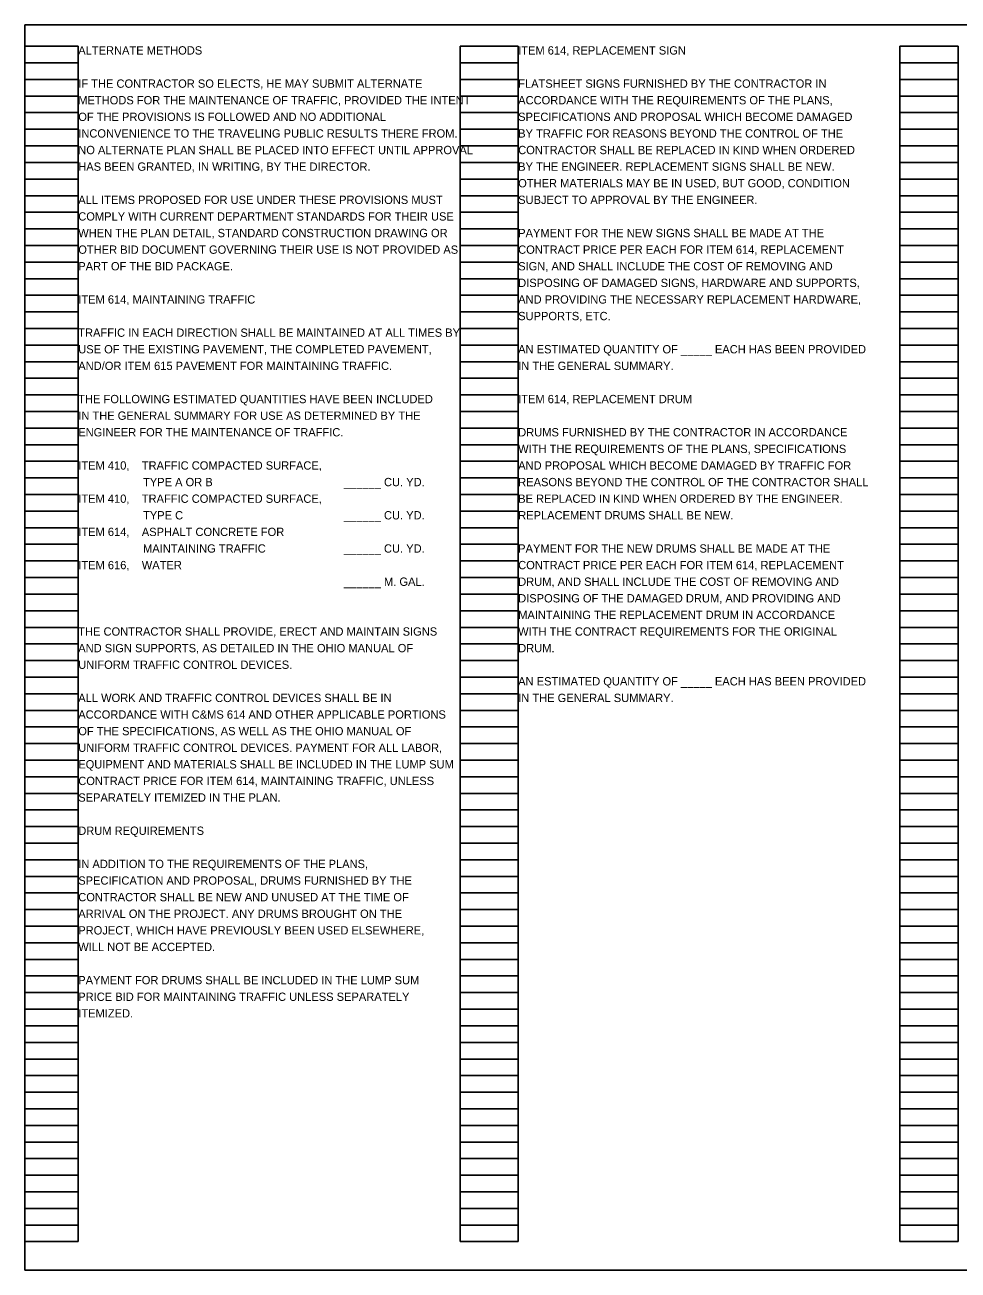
# Model space of a CAD drawing. Extents: x -34 to 2132911, y 0 to 658646.
# Drawn here: x 1.5 to 17.24, y 0.5 to 21.5 of the extents above; entities that cross this region are included whole.
import ezdxf

# ---------------------------------------------------------------- set-up
doc = ezdxf.new("R2010")
doc.units = 0
for name, color, linetype in [('SC_Scratch1', 7, 'Continuous'), ('SH_Data', 7, 'Continuous'), ('SH_Text', 7, 'Continuous')]:
    doc.layers.add(name, color=color, linetype=linetype)

msp = doc.modelspace()

# ---------------------------------------------------------------- linework, layer by layer
at = {"layer": 'SC_Scratch1'}
msp.add_lwpolyline([(1.5, 21.5), (32, 21.5), (32, 0.5), (1.5, 0.5)], close=True, dxfattribs=at)
at = {"layer": 'SH_Data'}
for p, q in [((1.5, 0.98), (1.5, 21.14)), ((1.5, 21.14), (2.4, 21.14)), ((2.4, 0.98), (2.4, 21.14)), ((8.84, 0.98), (8.84, 21.14)), ((8.84, 21.14), (9.82, 21.14)), ((9.82, 0.98), (9.82, 21.14)), ((16.26, 0.98), (16.26, 21.14)), ((16.26, 21.14), (17.24, 21.14)), ((17.24, 0.98), (17.24, 21.14)), ((1.5, 20.86), (2.4, 20.86)), ((8.84, 20.86), (9.82, 20.86)), ((16.26, 20.86), (17.24, 20.86)), ((1.5, 20.58), (2.4, 20.58)), ((8.84, 20.58), (9.82, 20.58)), ((16.26, 20.58), (17.24, 20.58)), ((1.5, 20.3), (2.4, 20.3)), ((8.84, 20.3), (9.82, 20.3)), ((16.26, 20.3), (17.24, 20.3)), ((1.5, 20.02), (2.4, 20.02)), ((8.84, 20.02), (9.82, 20.02)), ((16.26, 20.02), (17.24, 20.02)), ((1.5, 19.74), (2.4, 19.74)), ((8.84, 19.74), (9.82, 19.74)), ((16.26, 19.74), (17.24, 19.74)), ((1.5, 19.46), (2.4, 19.46)), ((8.84, 19.46), (9.82, 19.46)), ((16.26, 19.46), (17.24, 19.46)), ((1.5, 19.18), (2.4, 19.18)), ((8.84, 19.18), (9.82, 19.18)), ((16.26, 19.18), (17.24, 19.18)), ((1.5, 18.9), (2.4, 18.9)), ((8.84, 18.9), (9.82, 18.9)), ((16.26, 18.9), (17.24, 18.9)), ((1.5, 18.62), (2.4, 18.62)), ((8.84, 18.62), (9.82, 18.62)), ((16.26, 18.62), (17.24, 18.62)), ((1.5, 18.34), (2.4, 18.34)), ((8.84, 18.34), (9.82, 18.34)), ((16.26, 18.34), (17.24, 18.34)), ((1.5, 18.06), (2.4, 18.06)), ((8.84, 18.06), (9.82, 18.06)), ((16.26, 18.06), (17.24, 18.06)), ((1.5, 17.78), (2.4, 17.78)), ((8.84, 17.78), (9.82, 17.78)), ((16.26, 17.78), (17.24, 17.78)), ((1.5, 17.5), (2.4, 17.5)), ((8.84, 17.5), (9.82, 17.5)), ((16.26, 17.5), (17.24, 17.5)), ((1.5, 17.22), (2.4, 17.22)), ((8.84, 17.22), (9.82, 17.22)), ((16.26, 17.22), (17.24, 17.22)), ((1.5, 16.94), (2.4, 16.94)), ((8.84, 16.94), (9.82, 16.94)), ((16.26, 16.94), (17.24, 16.94)), ((1.5, 16.66), (2.4, 16.66)), ((8.84, 16.66), (9.82, 16.66)), ((16.26, 16.66), (17.24, 16.66)), ((1.5, 16.38), (2.4, 16.38)), ((8.84, 16.38), (9.82, 16.38)), ((16.26, 16.38), (17.24, 16.38)), ((1.5, 16.1), (2.4, 16.1)), ((8.84, 16.1), (9.82, 16.1)), ((16.26, 16.1), (17.24, 16.1)), ((1.5, 15.82), (2.4, 15.82)), ((8.84, 15.82), (9.82, 15.82)), ((16.26, 15.82), (17.24, 15.82)), ((1.5, 15.54), (2.4, 15.54)), ((8.84, 15.54), (9.82, 15.54)), ((16.26, 15.54), (17.24, 15.54)), ((1.5, 15.26), (2.4, 15.26)), ((8.84, 15.26), (9.82, 15.26)), ((16.26, 15.26), (17.24, 15.26)), ((1.5, 14.98), (2.4, 14.98)), ((8.84, 14.98), (9.82, 14.98)), ((16.26, 14.98), (17.24, 14.98)), ((1.5, 14.7), (2.4, 14.7)), ((8.84, 14.7), (9.82, 14.7)), ((16.26, 14.7), (17.24, 14.7)), ((1.5, 14.42), (2.4, 14.42)), ((8.84, 14.42), (9.82, 14.42)), ((16.26, 14.42), (17.24, 14.42)), ((1.5, 14.14), (2.4, 14.14)), ((8.84, 14.14), (9.82, 14.14)), ((16.26, 14.14), (17.24, 14.14)), ((1.5, 13.86), (2.4, 13.86)), ((8.84, 13.86), (9.82, 13.86)), ((16.26, 13.86), (17.24, 13.86)), ((1.5, 13.58), (2.4, 13.58)), ((8.84, 13.58), (9.82, 13.58)), ((16.26, 13.58), (17.24, 13.58)), ((1.5, 13.3), (2.4, 13.3)), ((8.84, 13.3), (9.82, 13.3)), ((16.26, 13.3), (17.24, 13.3)), ((1.5, 13.02), (2.4, 13.02)), ((8.84, 13.02), (9.82, 13.02)), ((16.26, 13.02), (17.24, 13.02)), ((1.5, 12.74), (2.4, 12.74)), ((8.84, 12.74), (9.82, 12.74)), ((16.26, 12.74), (17.24, 12.74)), ((1.5, 12.46), (2.4, 12.46)), ((8.84, 12.46), (9.82, 12.46)), ((16.26, 12.46), (17.24, 12.46)), ((1.5, 12.18), (2.4, 12.18)), ((8.84, 12.18), (9.82, 12.18)), ((16.26, 12.18), (17.24, 12.18)), ((1.5, 11.9), (2.4, 11.9)), ((8.84, 11.9), (9.82, 11.9)), ((16.26, 11.9), (17.24, 11.9)), ((1.5, 11.62), (2.4, 11.62)), ((8.84, 11.62), (9.82, 11.62)), ((16.26, 11.62), (17.24, 11.62)), ((1.5, 11.34), (2.4, 11.34)), ((8.84, 11.34), (9.82, 11.34)), ((16.26, 11.34), (17.24, 11.34)), ((1.5, 11.06), (2.4, 11.06)), ((8.84, 11.06), (9.82, 11.06)), ((16.26, 11.06), (17.24, 11.06)), ((1.5, 10.78), (2.4, 10.78)), ((8.84, 10.78), (9.82, 10.78)), ((16.26, 10.78), (17.24, 10.78)), ((1.5, 10.5), (2.4, 10.5)), ((8.84, 10.5), (9.82, 10.5)), ((16.26, 10.5), (17.24, 10.5)), ((1.5, 10.22), (2.4, 10.22)), ((8.84, 10.22), (9.82, 10.22)), ((16.26, 10.22), (17.24, 10.22)), ((1.5, 9.94), (2.4, 9.94)), ((8.84, 9.94), (9.82, 9.94)), ((16.26, 9.94), (17.24, 9.94)), ((1.5, 9.66), (2.4, 9.66)), ((8.84, 9.66), (9.82, 9.66)), ((16.26, 9.66), (17.24, 9.66)), ((1.5, 9.38), (2.4, 9.38)), ((8.84, 9.38), (9.82, 9.38)), ((16.26, 9.38), (17.24, 9.38)), ((1.5, 9.1), (2.4, 9.1)), ((8.84, 9.1), (9.82, 9.1)), ((16.26, 9.1), (17.24, 9.1)), ((1.5, 8.82), (2.4, 8.82)), ((8.84, 8.82), (9.82, 8.82)), ((16.26, 8.82), (17.24, 8.82)), ((1.5, 8.54), (2.4, 8.54)), ((8.84, 8.54), (9.82, 8.54)), ((16.26, 8.54), (17.24, 8.54)), ((1.5, 8.26), (2.4, 8.26)), ((8.84, 8.26), (9.82, 8.26)), ((16.26, 8.26), (17.24, 8.26)), ((1.5, 7.98), (2.4, 7.98)), ((8.84, 7.98), (9.82, 7.98)), ((16.26, 7.98), (17.24, 7.98)), ((1.5, 7.7), (2.4, 7.7)), ((8.84, 7.7), (9.82, 7.7)), ((16.26, 7.7), (17.24, 7.7)), ((1.5, 7.42), (2.4, 7.42)), ((8.84, 7.42), (9.82, 7.42)), ((16.26, 7.42), (17.24, 7.42)), ((1.5, 7.14), (2.4, 7.14)), ((8.84, 7.14), (9.82, 7.14)), ((16.26, 7.14), (17.24, 7.14)), ((1.5, 6.86), (2.4, 6.86)), ((8.84, 6.86), (9.82, 6.86)), ((16.26, 6.86), (17.24, 6.86)), ((1.5, 6.58), (2.4, 6.58)), ((8.84, 6.58), (9.82, 6.58)), ((16.26, 6.58), (17.24, 6.58)), ((1.5, 6.3), (2.4, 6.3)), ((8.84, 6.3), (9.82, 6.3)), ((16.26, 6.3), (17.24, 6.3)), ((1.5, 6.02), (2.4, 6.02)), ((8.84, 6.02), (9.82, 6.02)), ((16.26, 6.02), (17.24, 6.02)), ((1.5, 5.74), (2.4, 5.74)), ((8.84, 5.74), (9.82, 5.74)), ((16.26, 5.74), (17.24, 5.74)), ((1.5, 5.46), (2.4, 5.46)), ((8.84, 5.46), (9.82, 5.46)), ((16.26, 5.46), (17.24, 5.46)), ((1.5, 5.18), (2.4, 5.18)), ((8.84, 5.18), (9.82, 5.18)), ((16.26, 5.18), (17.24, 5.18)), ((1.5, 4.9), (2.4, 4.9)), ((8.84, 4.9), (9.82, 4.9)), ((16.26, 4.9), (17.24, 4.9)), ((1.5, 4.62), (2.4, 4.62)), ((8.84, 4.62), (9.82, 4.62)), ((16.26, 4.62), (17.24, 4.62)), ((1.5, 4.34), (2.4, 4.34)), ((8.84, 4.34), (9.82, 4.34)), ((16.26, 4.34), (17.24, 4.34)), ((1.5, 4.06), (2.4, 4.06)), ((8.84, 4.06), (9.82, 4.06)), ((16.26, 4.06), (17.24, 4.06)), ((1.5, 3.78), (2.4, 3.78)), ((8.84, 3.78), (9.82, 3.78)), ((16.26, 3.78), (17.24, 3.78)), ((1.5, 3.5), (2.4, 3.5)), ((8.84, 3.5), (9.82, 3.5)), ((16.26, 3.5), (17.24, 3.5)), ((1.5, 3.22), (2.4, 3.22)), ((8.84, 3.22), (9.82, 3.22)), ((16.26, 3.22), (17.24, 3.22)), ((1.5, 2.94), (2.4, 2.94)), ((8.84, 2.94), (9.82, 2.94)), ((16.26, 2.94), (17.24, 2.94)), ((1.5, 2.66), (2.4, 2.66)), ((8.84, 2.66), (9.82, 2.66)), ((16.26, 2.66), (17.24, 2.66)), ((1.5, 2.38), (2.4, 2.38)), ((8.84, 2.38), (9.82, 2.38)), ((16.26, 2.38), (17.24, 2.38)), ((1.5, 2.1), (2.4, 2.1)), ((8.84, 2.1), (9.82, 2.1)), ((16.26, 2.1), (17.24, 2.1)), ((1.5, 1.82), (2.4, 1.82)), ((8.84, 1.82), (9.82, 1.82)), ((16.26, 1.82), (17.24, 1.82)), ((1.5, 1.54), (2.4, 1.54)), ((8.84, 1.54), (9.82, 1.54)), ((16.26, 1.54), (17.24, 1.54)), ((1.5, 1.26), (2.4, 1.26)), ((8.84, 1.26), (9.82, 1.26)), ((16.26, 1.26), (17.24, 1.26)), ((1.5, 0.98), (2.4, 0.98)), ((8.84, 0.98), (9.82, 0.98)), ((16.26, 0.98), (17.24, 0.98))]:
    msp.add_line(p, q, dxfattribs=at)

# ---------------------------------------------------------------- texts
at = {"layer": 'SH_Text'}
for s, p in [('ALTERNATE METHODS', (2.4, 21)), ('ITEM 614, REPLACEMENT SIGN', (9.82, 21)), ('IF THE CONTRACTOR SO ELECTS, HE MAY SUBMIT ALTERNATE ', (2.4, 20.44)), ('FLATSHEET SIGNS FURNISHED BY THE CONTRACTOR IN', (9.82, 20.44)), ('METHODS FOR THE MAINTENANCE OF TRAFFIC, PROVIDED THE INTENT ', (2.4, 20.16)), ('ACCORDANCE WITH THE REQUIREMENTS OF THE PLANS,', (9.82, 20.16)), ('OF THE PROVISIONS IS FOLLOWED AND NO ADDITIONAL ', (2.4, 19.88)), ('SPECIFICATIONS AND PROPOSAL WHICH BECOME DAMAGED', (9.82, 19.88)), ('INCONVENIENCE TO THE TRAVELING PUBLIC RESULTS THERE FROM. ', (2.4, 19.6)), ('BY TRAFFIC FOR REASONS BEYOND THE CONTROL OF THE', (9.82, 19.6)), ('NO ALTERNATE PLAN SHALL BE PLACED INTO EFFECT UNTIL APPROVAL ', (2.4, 19.32)), ('CONTRACTOR SHALL BE REPLACED IN KIND WHEN ORDERED', (9.82, 19.32)), ('HAS BEEN GRANTED, IN WRITING, BY THE DIRECTOR.', (2.4, 19.04)), ('BY THE ENGINEER. REPLACEMENT SIGNS SHALL BE NEW.', (9.82, 19.04)), ('OTHER MATERIALS MAY BE IN USED, BUT GOOD, CONDITION', (9.82, 18.76)), ('ALL ITEMS PROPOSED FOR USE UNDER THESE PROVISIONS MUST ', (2.4, 18.48)), ('SUBJECT TO APPROVAL BY THE ENGINEER.', (9.82, 18.48)), ('COMPLY WITH CURRENT DEPARTMENT STANDARDS FOR THEIR USE ', (2.4, 18.2)), ('WHEN THE PLAN DETAIL, STANDARD CONSTRUCTION DRAWING OR ', (2.4, 17.92)), ('PAYMENT FOR THE NEW SIGNS SHALL BE MADE AT THE', (9.82, 17.92)), ('OTHER BID DOCUMENT GOVERNING THEIR USE IS NOT PROVIDED AS ', (2.4, 17.64)), ('CONTRACT PRICE PER EACH FOR ITEM 614, REPLACEMENT', (9.82, 17.64)), ('PART OF THE BID PACKAGE.', (2.4, 17.36)), ('SIGN, AND SHALL INCLUDE THE COST OF REMOVING AND', (9.82, 17.36)), ('DISPOSING OF DAMAGED SIGNS, HARDWARE AND SUPPORTS,', (9.82, 17.08)), ('ITEM 614, MAINTAINING TRAFFIC', (2.4, 16.8)), ('AND PROVIDING THE NECESSARY REPLACEMENT HARDWARE,', (9.82, 16.8)), ('SUPPORTS, ETC.', (9.82, 16.52)), ('TRAFFIC IN EACH DIRECTION SHALL BE MAINTAINED AT ALL TIMES BY', (2.4, 16.24)), ('USE OF THE EXISTING PAVEMENT, THE COMPLETED PAVEMENT,', (2.4, 15.96)), ('AN ESTIMATED QUANTITY OF _____ EACH HAS BEEN PROVIDED', (9.82, 15.96)), ('AND/OR ITEM 615 PAVEMENT FOR MAINTAINING TRAFFIC.', (2.4, 15.68)), ('IN THE GENERAL SUMMARY.', (9.82, 15.68)), ('THE FOLLOWING ESTIMATED QUANTITIES HAVE BEEN INCLUDED', (2.4, 15.12)), ('ITEM 614, REPLACEMENT DRUM', (9.82, 15.12)), ('IN THE GENERAL SUMMARY FOR USE AS DETERMINED BY THE', (2.4, 14.84)), ('ENGINEER FOR THE MAINTENANCE OF TRAFFIC.', (2.4, 14.56)), ('DRUMS FURNISHED BY THE CONTRACTOR IN ACCORDANCE', (9.82, 14.56)), ('WITH THE REQUIREMENTS OF THE PLANS, SPECIFICATIONS', (9.82, 14.28)), ('ITEM 410,    TRAFFIC COMPACTED SURFACE,', (2.4, 14)), ('AND PROPOSAL WHICH BECOME DAMAGED BY TRAFFIC FOR', (9.82, 14)), ('                     TYPE A OR B          ', (2.4, 13.72)), ('______ CU. YD.', (6.88, 13.72)), ('REASONS BEYOND THE CONTROL OF THE CONTRACTOR SHALL', (9.82, 13.72)), ('ITEM 410,    TRAFFIC COMPACTED SURFACE,', (2.4, 13.44)), ('BE REPLACED IN KIND WHEN ORDERED BY THE ENGINEER.', (9.82, 13.44)), ('                     TYPE C               ', (2.4, 13.16)), ('______ CU. YD.', (6.88, 13.16)), ('REPLACEMENT DRUMS SHALL BE NEW.', (9.82, 13.16)), ('ITEM 614,    ASPHALT CONCRETE FOR', (2.4, 12.88)), ('                     MAINTAINING TRAFFIC  ', (2.4, 12.6)), ('______ CU. YD.', (6.88, 12.6)), ('PAYMENT FOR THE NEW DRUMS SHALL BE MADE AT THE', (9.82, 12.6)), ('ITEM 616,    WATER', (2.4, 12.32)), ('CONTRACT PRICE PER EACH FOR ITEM 614, REPLACEMENT', (9.82, 12.32)), ('______ M. GAL.', (6.88, 12.04)), ('DRUM, AND SHALL INCLUDE THE COST OF REMOVING AND', (9.82, 12.04)), ('DISPOSING OF THE DAMAGED DRUM, AND PROVIDING AND', (9.82, 11.76)), ('MAINTAINING THE REPLACEMENT DRUM IN ACCORDANCE', (9.82, 11.48)), ('THE CONTRACTOR SHALL PROVIDE, ERECT AND MAINTAIN SIGNS', (2.4, 11.2)), ('WITH THE CONTRACT REQUIREMENTS FOR THE ORIGINAL', (9.82, 11.2)), ('AND SIGN SUPPORTS, AS DETAILED IN THE OHIO MANUAL OF', (2.4, 10.92)), ('DRUM.', (9.82, 10.92)), ('UNIFORM TRAFFIC CONTROL DEVICES.', (2.4, 10.64)), ('AN ESTIMATED QUANTITY OF _____ EACH HAS BEEN PROVIDED', (9.82, 10.36)), ('ALL WORK AND TRAFFIC CONTROL DEVICES SHALL BE IN', (2.4, 10.08)), ('IN THE GENERAL SUMMARY.', (9.82, 10.08)), ('ACCORDANCE WITH C&MS 614 AND OTHER APPLICABLE PORTIONS', (2.4, 9.8)), ('OF THE SPECIFICATIONS, AS WELL AS THE OHIO MANUAL OF', (2.4, 9.52)), ('UNIFORM TRAFFIC CONTROL DEVICES. PAYMENT FOR ALL LABOR,', (2.4, 9.24)), ('EQUIPMENT AND MATERIALS SHALL BE INCLUDED IN THE LUMP SUM', (2.4, 8.96)), ('CONTRACT PRICE FOR ITEM 614, MAINTAINING TRAFFIC, UNLESS', (2.4, 8.68)), ('SEPARATELY ITEMIZED IN THE PLAN.', (2.4, 8.4)), ('DRUM REQUIREMENTS', (2.4, 7.84)), ('IN ADDITION TO THE REQUIREMENTS OF THE PLANS,', (2.4, 7.28)), ('SPECIFICATION AND PROPOSAL, DRUMS FURNISHED BY THE', (2.4, 7)), ('CONTRACTOR SHALL BE NEW AND UNUSED AT THE TIME OF', (2.4, 6.72)), ('ARRIVAL ON THE PROJECT. ANY DRUMS BROUGHT ON THE', (2.4, 6.44)), ('PROJECT, WHICH HAVE PREVIOUSLY BEEN USED ELSEWHERE,', (2.4, 6.16)), ('WILL NOT BE ACCEPTED.', (2.4, 5.88)), ('PAYMENT FOR DRUMS SHALL BE INCLUDED IN THE LUMP SUM', (2.4, 5.32)), ('PRICE BID FOR MAINTAINING TRAFFIC UNLESS SEPARATELY', (2.4, 5.04)), ('ITEMIZED.', (2.4, 4.76))]:
    msp.add_text(s, height=0.14, dxfattribs=at).set_placement(p)

doc.saveas('drawing.dxf')
